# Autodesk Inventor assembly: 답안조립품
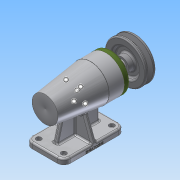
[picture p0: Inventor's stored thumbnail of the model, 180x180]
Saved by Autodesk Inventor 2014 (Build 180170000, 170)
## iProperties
Created: 2018-09
Part Number: 답안조립품
Document SubType Name: Assembly
Designer: Administrator
Author: Administrator
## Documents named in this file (11)
- C:\Users\Administrator\Desktop\480907V1003\답안조립품.iam
- C:\Users\Administrator\Desktop\480907V1003\본체.ipt
- C:\Users\Administrator\Desktop\480907V1003\커버.ipt
- C:\Users\Administrator\Desktop\480907V1003\베어링 6004.ipt
- C:\Users\Administrator\Desktop\480907V1003\축.ipt
- C:\Users\Administrator\Desktop\480907V1003\V벨트풀리.ipt
- C:\Users\Administrator\Desktop\480907V1003\키 5 x 5 x 16.ipt
- C:\Users\Administrator\Desktop\480907V1003\볼트 M4.ipt
- C:\Users\Administrator\Desktop\480907V1003\어댑터슬리브.ipt
- C:\Users\Administrator\Desktop\480907V1003\오일 실.ipt
- C:\Users\Administrator\Desktop\480907V1003\베어링 51202.ipt
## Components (1 placed, 1 different names)
1. V벨트풀리:1 — 각도:2
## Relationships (1: Angle 1)
- 각도:2 [Angle]: V벨트풀리:1
